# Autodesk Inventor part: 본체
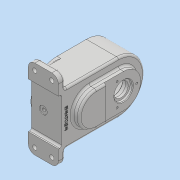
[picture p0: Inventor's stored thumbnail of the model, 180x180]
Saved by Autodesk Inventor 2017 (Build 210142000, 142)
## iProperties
Part Number: 본체
Material: 일반
Document SubType Name: Modeling
Designer: MRC
Density: 1 g/cm^3
Appearance: 기본값
Author: MRC
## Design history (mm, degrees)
sketch "스케치1"
  geometry: L1 (0, 40)-(-82, 40); L2 (-82, 40)-(-82, 61); L3 (-82, 61)-(-92, 61); L4 (-92, 61)-(-92, 35); L5 (-92, 35)-(-87, 35); L6 (-87, 35)-(-87, -35); L7 (-87, -35)-(-92, -35); L8 (-92, -35)-(-92, -61); L9 (-92, -61)-(-82, -61); L10 (-82, -61)-(-82, -40); L11 (-82, -40)-(0, -40); A1 r 40 centre (0, 0) between (0, -40) and (0, 40); 1 further point
  constraints: 22 end point, 6 perpendicular, 3 point on line, 2 horizontal, 2 point on circle, 2 tangent, 1 centre point, 1 coincident, 1 parallel, 1 vertical
  dimensions: "d0" = 80 diameter of A1; "d1" = 92 distance from line of L8 point (0, 0); "d2" = 10 distance of L8.end L9.end; "d3" = 70 distance between parallel lines of L7 L5; "d4" = 35 distance from line of L7 point (0, 0); "d5" = 5 distance between parallel lines of L8 L6; "d6" = 122 distance between parallel lines of L3 L9; "d7" = 61 distance from line of point (0, 0) L9
extrude "돌출1" new body sketch "스케치1" distance "d8" = 46; taper "d9" = 0 deg
sketch "스케치2"
  geometry: L1 (-40, 0)-(-40, -82) reference; L2 (40, -82)-(40, 0) reference; L3 (-40, -82)-(-40, 0) reference; L4 (-40, 0)-(-40, -45); L5 (40, 0)-(40, -45); A1 r 40 centre (0, 0) between (40, 0) and (-40, 0) reference; A2 r 40 centre (0, -45) between (-40, -45) and (40, -45); A3 r 40 centre (0, 0) between (40, 0) and (-40, 0); A4 r 40 centre (0, 0) between (40, 0) and (-40, 0) reference
  constraints: 6 end point, 4 point on circle, 2 centre point, 2 point on line, 2 tangent, 1 coincident, 1 concentric, 1 vertical
  dimensions: "d10" = 45 distance of A2.centre A1.centre
extrude "돌출2" join sketch "스케치2" distance "d11" = 3; taper "d12" = 0 deg
sketch "스케치3"
  geometry: L1 (0, 0)-(0, -45); L2 (-26, 0)-(-26, -45); L3 (26, -45)-(26, 0); A1 r 40 centre (0, 0) between (40, 0) and (-40, 0) reference; A2 r 26 centre (0, 0) between (26, 0) and (-26, 0); A3 r 26 centre (0, -45) between (-26, -45) and (26, -45); 1 further point
  constraints: 8 end point, 4 point on circle, 4 tangent, 2 centre point, 1 midpoint, 1 parallel, 1 vertical
  dimensions: "d13" = 52 diameter of A3; "d14" = 45 distance of L1.end L1.start
extrude "돌출3" join sketch "스케치3" distance "d15" = 11; taper "d16" = 0 deg
sketch "스케치4"
  geometry: L1 (-26, 0)-(-26, -45) reference; L2 (26, -45)-(26, 0) reference; L3 (-26, -30)-(26, -30); A1 r 26 centre (0, 0) between (26, 0) and (-26, 0) reference
  constraints: 2 end point, 2 point on line, 1 horizontal
  dimensions: "d17" = 30 distance from line of L3 A1.centre
extrude "돌출4" cut sketch "스케치4" distance "d18" = 3; taper "d19" = 0 deg
sketch "스케치5"
  geometry: L1 (0, 0)-(0, -45); L2 (30, 0)-(30, -45); L3 (-30, -45)-(-30, 0); A1 r 40 centre (0, 0) between (40, 0) and (-40, 0) reference; A2 r 40 centre (0, -45) between (-40, -45) and (40, -45) reference; A3 r 30 centre (0, 0) between (30, 0) and (-30, 0); A4 r 30 centre (0, -45) between (-30, -45) and (30, -45); 1 further point
  constraints: 8 end point, 4 point on circle, 4 tangent, 2 centre point, 1 midpoint, 1 parallel, 1 vertical
  dimensions: "d20" = 30 radius of A3
extrude "돌출5" cut sketch "스케치5" distance "d21" = 41; taper "d22" = 0 deg
hole "구멍1" diameter "d25" = 20; stored, may be unused: countersink angle "d29" = 90 deg, drill point angle "d31" = 0 deg; dims "d23" = 10, "d24" = 10, "d26" = 6, "d27" = 28, "d28" = 8, "d30" = 12
sketch "스케치6"
  geometry: C1 r 14 at (0, 0); A1 r 30 centre (0, 0) between (30, 0) and (-30, 0) reference
  constraints: 1 centre point, 1 coincident
  dimensions: "d32" = 28 diameter of C1
extrude "돌출6" cut sketch "스케치6" distance "d33" = 8; taper "d34" = 0 deg
hole "구멍2" diameter "d37" = 22; stored, may be unused: countersink angle "d41" = 90 deg, drill point angle "d43" = 0 deg; dims "d35" = 10, "d36" = 10, "d38" = 6, "d39" = 28, "d40" = 4, "d42" = 20
node "작업 평면2"
sketch "스케치8"
  geometry: L1 (-3, 5)-(-3, -75) reference; C1 r 6 at (18, -35); 1 further point
  constraints: 1 centre point, 1 horizontal alignment
  dimensions: "d45" = 12 diameter of C1; "d46" = 21 distance from line of L1 C1.centre
extrude "돌출7" join sketch "스케치8" stored distance "d47" = 8; taper "d48" = 0 deg
sketch "스케치9"
  geometry: C1 r 6 at (0, 0) reference; 1 further point
hole "구멍3" sketch "스케치9" at (0, 0) diameter "d49" = 4.917; stored, may be unused: countersink angle "d53" = 90 deg, drill point angle "d55" = 118 deg; dims "d50" = 12, "d51" = 19.05, "d52" = 4.775, "d54" = 17.1
sketch "스케치10"
  geometry: L1 (0, 0)-(0, 70) reference; L2 (-3, 75)-(-3, -5) reference; 3 further points
  constraints: 1 horizontal alignment, 1 midpoint
  dimensions: "d56" = 21 distance from line of L2 point (18, 35)
hole "구멍4" sketch "스케치10" at (18, 35) diameter "d57" = 4.917; stored, may be unused: countersink angle "d61" = 90 deg, drill point angle "d63" = 118 deg; dims "d58" = 12, "d59" = 12, "d60" = 1, "d62" = 17.1
sketch "스케치11"
  geometry: L1 (0, 0)-(0, -45); L2 (35, 0)-(35, -45); L3 (-35, -45)-(-35, 0); C1 r 11 at (0, 0) reference; A1 r 40 centre (0, -45) between (-40, -45) and (40, -45) reference; A2 r 35 centre (0, 0) between (35, 0) and (-35, 0); A3 r 35 centre (0, -45) between (-35, -45) and (35, -45); 7 further points
  constraints: 8 end point, 6 point on circle, 4 coincident, 4 tangent, 2 centre point, 1 midpoint, 1 parallel, 1 vertical
  dimensions: "d64" = 35 radius of A2
hole "구멍5" sketch "스케치11" at (0, 35), (-35, 0), (35, 0), (35, -45), (0, -80), (-35, -45) diameter "d65" = 3.242; stored, may be unused: countersink angle "d69" = 90 deg, drill point angle "d71" = 118 deg; dims "d66" = 8, "d67" = 12, "d68" = 1, "d70" = 10
sketch "스케치12"
  geometry: C1 r 14 at (0, 0) reference; 1 further point
  constraints: 1 vertical alignment
  dimensions: "d72" = 20 distance of point (0, 20) C1.centre
hole "구멍6" sketch "스케치12" at (0, 20) diameter "d73" = 3.242; stored, may be unused: countersink angle "d77" = 90 deg, drill point angle "d79" = 118 deg; dims "d74" = 8, "d75" = 12, "d76" = 1, "d78" = 10
fillet "모깎기1" dims "d83" = 10
sketch "스케치13"
  geometry: L1 (10, 101)-(36, 101) reference; L2 (0, 80)-(0, 91) reference; L3 (0, 80)-(46, 80) reference; L4 (46, 91)-(46, 80) reference; A1 r 10 centre (36, -11) between (36, -21) and (46, -11) reference; A2 r 10 centre (10, -11) between (0, -11) and (10, -21) reference; A3 r 10 centre (36, 91) between (46, 91) and (36, 101) reference; A4 r 10 centre (10, 91) between (10, 101) and (0, 91) reference; 1 further point
hole "구멍7" sketch "스케치13" at (36, -11), (10, -11), (10, 91), (36, 91) diameter "d84" = 6.6; stored, may be unused: countersink angle "d88" = 90 deg, drill point angle "d90" = 118 deg; dims "d85" = 8, "d86" = 11, "d87" = 2, "d89" = 20
fillet "모깎기2" dims "d91" = 3
fillet "모깎기3" dims "d92" = 5
fillet "모깎기4" dims "d93" = 0.3
fillet "모깎기5" dims "d94" = 3
fillet "모깎기6" dims "d95" = 3
chamfer "모따기1" distance "d96" = 1; stored, may be unused: second distance "d97" = 2, angle "d98" = 45 deg
sketch "스케치14"
  geometry: L1 (-32, -87)-(32, -87) reference; L2 (-51, -92)-(-61, -92) reference; 2 further points
  constraints: 1 midpoint, 1 vertical alignment, 1 other
  dimensions: "d100" = 12 distance from line of L2 point (0, -80)
feature "엠보싱1" sketch "스케치14" dims "d0" = 80, "d1" = 92, "d2" = 10, "d3" = 70, "d4" = 35, "d5" = 5, "d6" = 122, "d7" = 61, "d10" = 45, "d101" = 0.5, "d102" = 0
node "솔리드1"
pattern_circular "원형 패턴1" dims angle "d81" = 360 deg
node "투영된 루프1"
other parameters: "d44" = -135
